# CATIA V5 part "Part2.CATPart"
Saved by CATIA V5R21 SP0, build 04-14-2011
Part number: Part2
Bounding box of the stored display mesh (mm): x -29.913 to 29.913, y -29.913 to 29.913, z -89.119 to 0
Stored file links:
  D:\CATIA V5R21 E-RESOURCES\CATIA-V5R21\catia-v5r21-Prts\c12_catia_v5r21_prt\c12_catia_v5r21figr_12-35\Part2.CATPart
  C:\CATIA-V5R13-manuscript\catia-v5r13-solid-models-090204\c11\Figure 11-35\Figure 11-35.CATProduct
  D:\CATIA V5R21 E-RESOURCES\CATIA-V5R21\catia-v5r21-Prts\c12_catia_v5r21_prt\c12_catia_v5r21figr_12-35\Base.CATPart
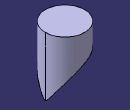
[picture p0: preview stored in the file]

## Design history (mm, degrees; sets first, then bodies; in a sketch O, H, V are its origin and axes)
Set1
  DatumSurface1: linked copy from another document
Body1 (main body)
  Sketch1 on xy-plane, origin (0, 0, 0), H (1, 0, 0), V (0, 1, 0)
    circle A1 centre (0, 0) radius 29.9132
  Pad1: profile Sketch1, direction (0, 0, 1), up to face of DatumSurface1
